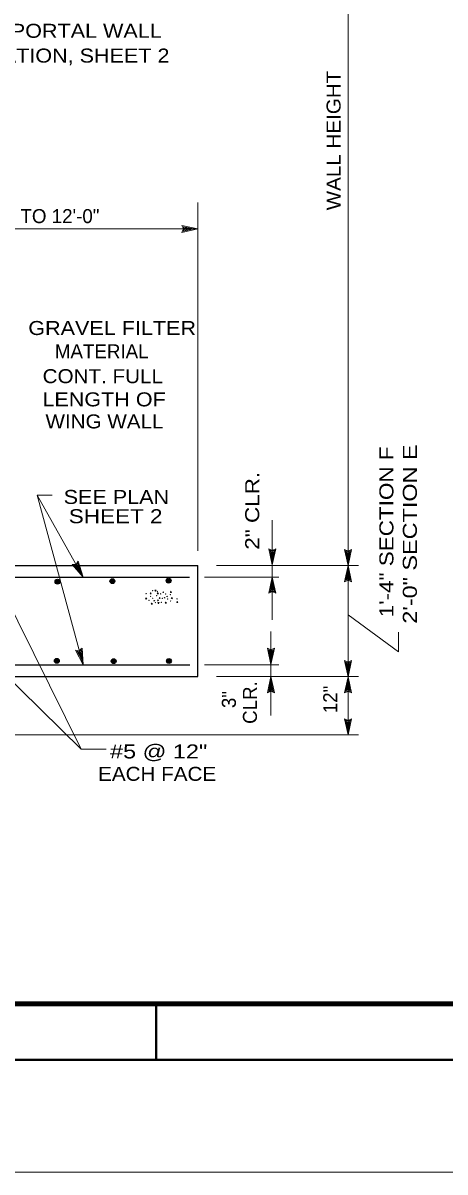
# Model space of a CAD drawing. Extents: x -28.1 to 13.9, y -16.1 to 13.9.
# Drawn here: x -4.33 to -0.57, y -16.13 to -5.87 of the extents above; entities that cross this region are included whole.
import ezdxf
from ezdxf.enums import TextEntityAlignment as Align

# ---------------------------------------------------------------- set-up
doc = ezdxf.new("R2010")
doc.units = 0
doc.header["$LTSCALE"] = 0.05
doc.layers.add('1', color=7, linetype='Continuous', lineweight=13)
doc.layers.add('2', color=7, linetype='Continuous', lineweight=13)

msp = doc.modelspace()

# ---------------------------------------------------------------- linework, layer by layer
at = {"layer": '1'}
for p, q in [((-1.43204, -10.71431), (-1.43204, -2.71131)), ((-2.77004, -10.58231), (-2.77004, -7.47131)), ((-2.77004, -7.70831), (-2.91404, -7.67731)), ((-2.80704, -7.70831), (-2.90104, -7.68831)), ((-2.89204, -7.70831), (-2.90104, -7.68831)), ((-8.88204, -7.70831), (-2.77004, -7.70831)), ((-2.77004, -7.70831), (-2.91404, -7.73931)), ((-2.80704, -7.70831), (-2.90104, -7.72831)), ((-2.90104, -7.72831), (-2.89204, -7.70831)), ((-2.84304, -7.70831), (-2.88804, -7.69931)), ((-2.88404, -7.70831), (-2.88804, -7.69931)), ((-2.84304, -7.70831), (-2.88804, -7.71831)), ((-2.88804, -7.71831), (-2.88404, -7.70831)), ((-4.20304, -10.08431), (-4.07104, -10.08431)), ((-4.20304, -10.08431), (-3.79404, -11.59831)), ((-4.20304, -10.08431), (-3.79404, -10.81631)), ((-2.10704, -10.70831), (-2.13804, -10.56431)), ((-2.10704, -10.70831), (-2.07604, -10.56431)), ((-2.10704, -10.67131), (-2.12704, -10.57731)), ((-2.12704, -10.57731), (-2.10704, -10.58631)), ((-2.10704, -10.63531), (-2.11704, -10.59031)), ((-2.11704, -10.59031), (-2.10704, -10.59431)), ((-2.10704, -10.67131), (-2.08704, -10.57731)), ((-2.10704, -10.58631), (-2.08704, -10.57731)), ((-2.10704, -10.63531), (-2.09804, -10.59031)), ((-2.10704, -10.59431), (-2.09804, -10.59031)), ((-1.43204, -10.71431), (-1.46304, -10.57031)), ((-1.43204, -10.67731), (-1.45204, -10.58331)), ((-1.45204, -10.58331), (-1.43204, -10.59231)), ((-1.43204, -10.64131), (-1.44204, -10.59631)), ((-1.44204, -10.59631), (-1.43204, -10.60031)), ((-1.43204, -10.71431), (-1.40104, -10.57031)), ((-1.43204, -10.67731), (-1.41204, -10.58331)), ((-1.43204, -10.59231), (-1.41204, -10.58331)), ((-1.43204, -10.64131), (-1.42304, -10.59631)), ((-1.43204, -10.60031), (-1.42304, -10.59631)), ((-3.79404, -10.81631), (-3.89104, -10.70531)), ((-3.87504, -10.71131), (-3.85404, -10.70931)), ((-3.81204, -10.78431), (-3.87504, -10.71131)), ((-3.86004, -10.71831), (-3.85004, -10.71631)), ((-3.83004, -10.75231), (-3.86004, -10.71831)), ((-3.85404, -10.70931), (-3.84004, -10.69231)), ((-3.85004, -10.71631), (-3.84404, -10.70931)), ((-3.83004, -10.75231), (-3.84404, -10.70931)), ((-3.81204, -10.78431), (-3.84004, -10.69231)), ((-3.79404, -10.81631), (-3.83704, -10.67531)), ((-2.60504, -10.71431), (-1.33704, -10.71431)), ((-1.43204, -10.71431), (-1.46304, -10.85831)), ((-1.43204, -10.75131), (-1.45204, -10.84531)), ((-1.43204, -10.71431), (-1.40104, -10.85831)), ((-1.43204, -10.75131), (-1.41204, -10.84531)), ((-2.71104, -10.81631), (-2.04804, -10.81631)), ((-2.10704, -10.81631), (-2.13804, -10.96031)), ((-2.10704, -10.85331), (-2.12704, -10.94731)), ((-2.10704, -10.81631), (-2.07604, -10.96031)), ((-2.10704, -10.85331), (-2.08704, -10.94731)), ((-1.43204, -10.83631), (-1.45204, -10.84531)), ((-1.43204, -10.78731), (-1.44104, -10.83231)), ((-1.43204, -10.82831), (-1.44104, -10.83231)), ((-1.43204, -10.78731), (-1.42204, -10.83231)), ((-1.42204, -10.83231), (-1.43204, -10.82831)), ((-1.41204, -10.84531), (-1.43204, -10.83631)), ((-3.81304, -12.35331), (-4.51504, -10.92831)), ((-2.10704, -10.93831), (-2.12704, -10.94731)), ((-2.10704, -10.88931), (-2.11604, -10.93431)), ((-2.10704, -10.93031), (-2.11604, -10.93431)), ((-2.10704, -10.88931), (-2.09704, -10.93431)), ((-2.09704, -10.93431), (-2.10704, -10.93031)), ((-2.08704, -10.94731), (-2.10704, -10.93831)), ((-0.98304, -11.48331), (-1.43204, -11.15331)), ((-0.98304, -11.48331), (-0.98304, -11.30931)), ((-3.79404, -11.59831), (-3.86104, -11.46731)), ((-3.80404, -11.56231), (-3.84704, -11.47731)), ((-3.84704, -11.47731), (-3.82604, -11.48031)), ((-3.81304, -11.52831), (-3.83404, -11.48731)), ((-3.83404, -11.48731), (-3.82404, -11.48831)), ((-3.82604, -11.48031), (-3.80904, -11.46631)), ((-3.82404, -11.48831), (-3.81604, -11.48231)), ((-3.81304, -11.52831), (-3.81604, -11.48231)), ((-3.80404, -11.56231), (-3.80904, -11.46631)), ((-3.79404, -11.59831), (-3.80204, -11.45131)), ((-2.11904, -11.59531), (-2.15004, -11.45131)), ((-2.11904, -11.55831), (-2.13904, -11.46431)), ((-2.13904, -11.46431), (-2.11904, -11.47331)), ((-2.11904, -11.52231), (-2.12904, -11.47731)), ((-2.12904, -11.47731), (-2.11904, -11.48131)), ((-2.11904, -11.59531), (-2.08804, -11.45131)), ((-2.11904, -11.55831), (-2.09904, -11.46431)), ((-2.11904, -11.47331), (-2.09904, -11.46431)), ((-2.11904, -11.52231), (-2.11004, -11.47731)), ((-2.11904, -11.48131), (-2.11004, -11.47731)), ((-1.43204, -11.70631), (-1.46304, -11.56231)), ((-1.43204, -11.66931), (-1.45204, -11.57531)), ((-1.45204, -11.57531), (-1.43204, -11.58431)), ((-1.43204, -11.63331), (-1.44204, -11.58831)), ((-1.44204, -11.58831), (-1.43204, -11.59231)), ((-1.43204, -11.70631), (-1.40104, -11.56231)), ((-1.43204, -11.66931), (-1.41204, -11.57531)), ((-1.43204, -11.58431), (-1.41204, -11.57531)), ((-1.43204, -11.63331), (-1.42304, -11.58831)), ((-1.43204, -11.59231), (-1.42304, -11.58831)), ((-3.81304, -12.35331), (-4.53304, -11.64031)), ((-2.71104, -11.59831), (-2.04804, -11.59831)), ((-2.60504, -11.70531), (-1.33704, -11.70531)), ((-2.11904, -11.70531), (-2.15004, -11.84931)), ((-2.11904, -11.74231), (-2.13904, -11.83631)), ((-2.11904, -11.77831), (-2.12804, -11.82331)), ((-2.11904, -11.70531), (-2.08804, -11.84931)), ((-2.11904, -11.74231), (-2.09904, -11.83631)), ((-2.11904, -11.77831), (-2.10904, -11.82331)), ((-1.43204, -11.70631), (-1.46304, -11.85031)), ((-1.43204, -11.74331), (-1.45204, -11.83731)), ((-1.43204, -11.77931), (-1.44104, -11.82431)), ((-1.43204, -11.70631), (-1.40104, -11.85031)), ((-1.43204, -11.74331), (-1.41204, -11.83731)), ((-1.43204, -11.77931), (-1.42204, -11.82431)), ((-2.11904, -11.82731), (-2.13904, -11.83631)), ((-2.11904, -11.81931), (-2.12804, -11.82331)), ((-2.10904, -11.82331), (-2.11904, -11.81931)), ((-2.09904, -11.83631), (-2.11904, -11.82731)), ((-1.43204, -11.82831), (-1.45204, -11.83731)), ((-1.43204, -11.82031), (-1.44104, -11.82431)), ((-1.42204, -11.82431), (-1.43204, -11.82031)), ((-1.41204, -11.83731), (-1.43204, -11.82831)), ((-1.43204, -12.22531), (-1.46304, -12.08131)), ((-1.43204, -12.18831), (-1.45204, -12.09431)), ((-1.45204, -12.09431), (-1.43204, -12.10331)), ((-1.43204, -12.22531), (-1.40104, -12.08131)), ((-1.43204, -12.18831), (-1.41204, -12.09431)), ((-1.43204, -12.10331), (-1.41204, -12.09431)), ((-1.43204, -12.15231), (-1.44204, -12.10731)), ((-1.44204, -12.10731), (-1.43204, -12.11131)), ((-1.43204, -12.15231), (-1.42304, -12.10731)), ((-1.43204, -12.11131), (-1.42304, -12.10731)), ((-6.66904, -12.22431), (-1.33704, -12.22431)), ((-3.81304, -12.35331), (-3.58904, -12.35331)), ((13.85696, -16.12731), (-28.14304, -16.12731))]:
    msp.add_line(p, q, dxfattribs=at)
at = {"layer": '1', "lineweight": 25}
for p, q in [((-6.79004, -10.71431), (-2.77004, -10.71431)), ((-2.77004, -11.70431), (-2.77004, -10.71431)), ((-8.78204, -10.81631), (-2.84404, -10.81631)), ((-8.77404, -11.59831), (-2.84304, -11.59831)), ((-6.78704, -11.70531), (-2.77004, -11.70531))]:
    msp.add_line(p, q, dxfattribs=at)
at = {"layer": '1', "lineweight": 40}
msp.add_line((-3.14304, -14.62731), (-3.14304, -15.12731), dxfattribs=at)
msp.add_lwpolyline([(-27.14304, -15.12731), (-27.14304, 12.87269), (12.85696, 12.87269), (12.85696, -15.12731)], close=True, dxfattribs=at)
at = {"layer": '1', "lineweight": 90}
msp.add_lwpolyline([(-25.64304, 12.37269), (12.35696, 12.37269), (12.35696, -14.62731), (-25.64304, -14.62731)], close=True, dxfattribs=at)
at = {"layer": '1'}
for points in [[(-2.91404, -7.73931), (-2.90004, -7.70831), (-2.91404, -7.67731)], [(-2.10704, -11.19831), (-2.10704, -10.81631), (-2.10704, -10.70831), (-2.10704, -10.30931)], [(-2.13804, -10.56431), (-2.10704, -10.57831), (-2.07604, -10.56431)], [(-1.46304, -10.57031), (-1.43204, -10.58431), (-1.40104, -10.57031)], [(-3.89104, -10.70531), (-3.85704, -10.70331), (-3.83704, -10.67531)], [(-1.43204, -10.71431), (-1.43204, -11.70631), (-1.43204, -12.22531)], [(-1.40104, -10.85831), (-1.43204, -10.84431), (-1.46304, -10.85831)], [(-2.07604, -10.96031), (-2.10704, -10.94631), (-2.13804, -10.96031)], [(-2.11904, -12.05131), (-2.11904, -11.70531), (-2.11904, -11.59531), (-2.11904, -11.30331)], [(-3.86104, -11.46731), (-3.82804, -11.47231), (-3.80204, -11.45131)], [(-2.15004, -11.45131), (-2.11904, -11.46531), (-2.08804, -11.45131)], [(-1.46304, -11.56231), (-1.43204, -11.57631), (-1.40104, -11.56231)], [(-2.08804, -11.84931), (-2.11904, -11.83531), (-2.15004, -11.84931)], [(-1.40104, -11.85031), (-1.43204, -11.83631), (-1.46304, -11.85031)], [(-1.46304, -12.08131), (-1.43204, -12.09531), (-1.40104, -12.08131)]]:
    msp.add_lwpolyline(points, dxfattribs=at)
at = {"layer": '1', "lineweight": 25}
for centre, radius in [((-4.02199, -10.85723), 0.02168), ((-4.02199, -10.85723), 0.01681), ((-4.02199, -10.85723), 0.01233), ((-4.02199, -10.85723), 0.00623), ((-3.53299, -10.85323), 0.02168), ((-3.53299, -10.85323), 0.01681), ((-3.53299, -10.85323), 0.01233), ((-3.53299, -10.85323), 0.00623), ((-3.03199, -10.84823), 0.02168), ((-3.03199, -10.84823), 0.01681), ((-3.03199, -10.84823), 0.01233), ((-3.03199, -10.84823), 0.00623), ((-4.02799, -11.56423), 0.02168), ((-4.02799, -11.56423), 0.01681), ((-4.02799, -11.56423), 0.01233), ((-4.02799, -11.56423), 0.00623), ((-3.52199, -11.56723), 0.02168), ((-3.52199, -11.56723), 0.01681), ((-3.52199, -11.56723), 0.01233), ((-3.52199, -11.56723), 0.00623), ((-3.02899, -11.56523), 0.02168), ((-3.02899, -11.56523), 0.01681), ((-3.02899, -11.56523), 0.01233), ((-3.02899, -11.56523), 0.00623)]:
    msp.add_circle(centre, radius, dxfattribs=at)
at = {"layer": '2'}
msp.add_line((-3.08404, -10.95331), (-3.07804, -10.94831), dxfattribs=at)
for points in [[(-3.19104, -10.95631), (-3.19604, -10.96631), (-3.18604, -10.96731), (-3.19404, -10.95631)], [(-3.15004, -10.94131), (-3.15504, -10.93231), (-3.14404, -10.93231), (-3.15004, -10.94331)], [(-3.12904, -10.95531), (-3.13404, -10.96531), (-3.12304, -10.96631), (-3.13104, -10.95531)], [(-3.07804, -10.94831), (-3.07604, -10.95531), (-3.08404, -10.95531)], [(-3.01104, -10.94331), (-3.01604, -10.95331), (-3.00604, -10.95431), (-3.01404, -10.94331)], [(-3.23304, -11.01231), (-3.23804, -11.00431), (-3.22704, -11.00431), (-3.23304, -11.01431)], [(-3.18104, -11.04831), (-3.18604, -11.05831), (-3.17604, -11.05931), (-3.18404, -11.04831)], [(-3.16404, -11.02731), (-3.15904, -11.02431), (-3.15504, -11.02731), (-3.16704, -11.02931)], [(-3.12204, -11.05331), (-3.12704, -11.04431), (-3.11604, -11.04431), (-3.12204, -11.05431)], [(-3.07104, -11.00131), (-3.06804, -10.99731), (-3.06304, -11.00131), (-3.07004, -11.00231)], [(-3.05704, -11.03931), (-3.06204, -11.04931), (-3.05204, -11.05031), (-3.06004, -11.03931)], [(-3.05104, -10.98831), (-3.04604, -10.98631), (-3.04304, -10.99231), (-3.05104, -10.98931)], [(-3.00304, -11.00831), (-3.00804, -11.00031), (-2.99704, -11.00031), (-3.00304, -11.01031)], [(-2.95404, -11.03231), (-2.95904, -11.04231), (-2.94904, -11.04331), (-2.95604, -11.03231)]]:
    msp.add_lwpolyline(points, dxfattribs=at)
for points in [[(-3.13104, -11.02731), (-3.12604, -11.01931), (-3.12304, -11.02531)], [(-3.11604, -11.00631), (-3.11104, -10.99731), (-3.10804, -11.00331)]]:
    msp.add_lwpolyline(points, close=True, dxfattribs=at)
for centre in [(-3.23204, -10.96419), (-3.17379, -10.93744), (-3.13104, -10.94419), (-3.10329, -10.96594), (-3.05704, -10.96694), (-3.01579, -10.97269), (-3.20754, -11.02319), (-3.19229, -10.98944), (-3.17304, -11.00469), (-3.14954, -11.04344), (-3.13854, -10.98119), (-3.09554, -11.04094), (-3.08804, -11.00644), (-3.04004, -11.01219), (-3.01479, -11.02994), (-2.95754, -11.01044)]:
    msp.add_circle(centre, 0.00162, dxfattribs=at)

# ---------------------------------------------------------------- texts
at = {"layer": '1'}
for s, width, p in [('SEE PORTAL WALL', 1.15, (-4.87704, -6.00231)), ('GRAVEL FILTER', 1.15, (-4.28304, -8.65531)), ('#5 @ 12"', 1.25, (-3.55404, -12.43531))]:
    msp.add_text(s, height=0.125, dxfattribs=dict(at, width=width)).set_placement(p)
for s, width, p in [('ELEVATION, SHEET 2', 1.15, (-4.01748, -6.22331)), ('CONT. FULL', 1.1, (-3.61864, -9.08531)), ('LENGTH OF', 1.15, (-3.60719, -9.29231)), ('WING WALL', 1.1, (-3.60351, -9.48931)), ('SEE PLAN', 1.15, (-3.49748, -10.16331)), ('SHEET 2', 1.2, (-3.50415, -10.33531)), ('EACH FACE', 1.1, (-3.1341, -12.63531))]:
    msp.add_text(s, height=0.125, dxfattribs=dict(at, width=width)).set_placement(p, align=Align.CENTER)
for s, width, p in [('WALL HEIGHT', 1.1, (-1.49804, -6.91931)), ('1\'-4" SECTION F', 1.2, (-1.02704, -10.41232))]:
    msp.add_text(s, height=0.125, rotation=90, dxfattribs=dict(at, width=width)).set_placement(p, align=Align.CENTER)
for s, p in [('VARIES 2\'-6" TO 12\'-0"', (-4.52025, -7.65631)), ('MATERIAL', (-3.62844, -8.86331))]:
    msp.add_text(s, height=0.125, dxfattribs=at).set_placement(p, align=Align.CENTER)
for s, width, p in [('2\'-0" SECTION E', 1.25, (-0.81804, -11.23231)), ('2" CLR.', 1.2, (-2.22404, -10.57231))]:
    msp.add_text(s, height=0.125, rotation=90, dxfattribs=dict(at, width=width)).set_placement(p)
for s, p in [('CLR.', (-2.24404, -11.93641)), ('3"', (-2.43204, -11.90973))]:
    msp.add_text(s, height=0.125, rotation=90, dxfattribs=at).set_placement(p, align=Align.CENTER)
msp.add_text('12"', height=0.125, rotation=90, dxfattribs=at).set_placement((-1.52804, -11.78628), align=Align.RIGHT)

doc.saveas('drawing.dxf')
